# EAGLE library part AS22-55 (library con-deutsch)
DEUTSCH Connector
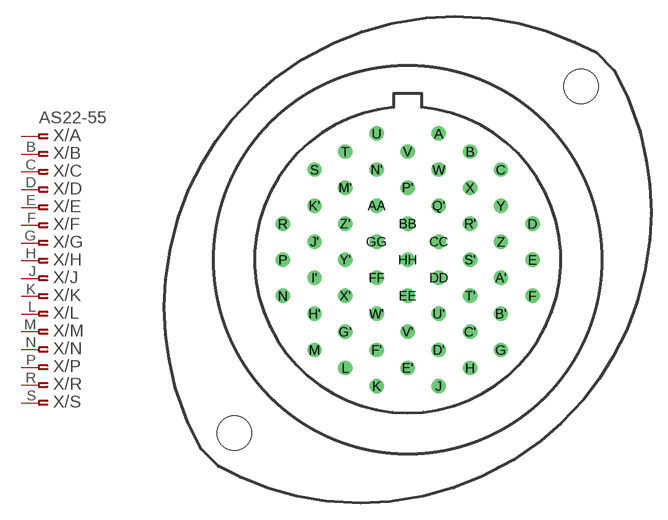
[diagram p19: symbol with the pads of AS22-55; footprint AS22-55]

Designator prefix X; gates /A=PINF_VAL /B=ASPINF /C=ASPINF /D=ASPINF /E=ASPINF /F=ASPINF /G=ASPINF /H=ASPINF /J=ASPINF /K=ASPINF /L=ASPINF /M=ASPINF /N=ASPINF /P=ASPINF /R=ASPINF /S=ASPINF /T=ASPINF /U=ASPINF /V=ASPINF /W=ASPINF /X=ASPINF /Y=ASPINF /Z=ASPINF /A'=PINF_VAL /B'=ASPINF /C'=ASPINF /D'=ASPINF /E'=ASPINF /F'=ASPINF /G'=ASPINF /H'=ASPINF /J'=ASPINF /K'=ASPINF /I'=ASPINF /M'=ASPINF /N'=ASPINF /P'=ASPINF /R'=ASPINF /S'=ASPINF /T'=ASPINF /U'=ASPINF /V'=ASPINF /W'=ASPINF /X'=ASPINF /Y'=ASPINF /Z'=ASPINF /Q'=ASPINF /AA=PINF_VAL /BB=ASPINF /CC=ASPINF /DD=ASPINF /EE=ASPINF /FF=ASPINF /GG=ASPINF /HH=ASPINF

## AS22-55 (OC_FARNELL: unknown; OC_NEWARK: unknown)  [AS22-55]
A  /A:1  pas
A'  /A':1  pas
AA  /AA:1  pas
B  /B:1  pas
B'  /B':1  pas
BB  /BB:1  pas
C  /C:1  pas
C'  /C':1  pas
CC  /CC:1  pas
D  /D:1  pas
D'  /D':1  pas
DD  /DD:1  pas
E  /E:1  pas
E'  /E':1  pas
EE  /EE:1  pas
F  /F:1  pas
F'  /F':1  pas
FF  /FF:1  pas
G  /G:1  pas
G'  /G':1  pas
GG  /GG:1  pas
H  /H:1  pas
H'  /H':1  pas
HH  /HH:1  pas
I'  /I':1  pas
J  /J:1  pas
J'  /J':1  pas
K  /K:1  pas
K'  /K':1  pas
L  /L:1  pas
M  /M:1  pas
M'  /M':1  pas
N  /N:1  pas
N'  /N':1  pas
P  /P:1  pas
P'  /P':1  pas
Q'  /Q':1  pas
R  /R:1  pas
R'  /R':1  pas
S  /S:1  pas
S'  /S':1  pas
T  /T:1  pas
T'  /T':1  pas
U  /U:1  pas
U'  /U':1  pas
V  /V:1  pas
V'  /V':1  pas
W  /W:1  pas
W'  /W':1  pas
X  /X:1  pas
X'  /X':1  pas
Y  /Y:1  pas
Y'  /Y':1  pas
Z  /Z:1  pas
Z'  /Z':1  pas

## Footprint AS22-55 (pad centres in mm)
DEUTSCH Connector
drill 0.813 round: A 2.845,11.557; A' 8.534,-1.651; AA -2.845,4.953; B 5.715,9.906; B' 8.534,-4.953; BB 0,3.302; C 8.534,8.255; C' 5.715,-6.604; CC 2.845,1.651; D 11.43,3.302; D' 2.845,-8.255; DD 2.845,-1.651; E 11.43,0; E' 0,-9.906; EE 0,-3.302; F 11.43,-3.302; F' -2.845,-8.255; FF -2.845,-1.651; G 8.534,-8.255; G' -5.715,-6.604; GG -2.845,1.651; H 5.715,-9.906; H' -8.534,-4.953; HH 0,0; I' -8.534,-1.651; J 2.845,-11.557; J' -8.534,1.651; K -2.845,-11.557; K' -8.534,4.953; L -5.715,-9.906; M -8.534,-8.255; M' -5.715,6.604; N -11.43,-3.302; N' -2.845,8.255; P -11.43,0; P' 0,6.604; Q' 2.845,4.953; R -11.43,3.302; R' 5.715,3.302; S -8.534,8.255; S' 5.715,0; T -5.715,9.906; T' 5.715,-3.302; U -2.845,11.557; U' 2.845,-4.953; V 0,9.906; V' 0,-6.604; W 2.845,8.255; W' -2.845,-4.953; X 5.715,6.604; X' -5.715,-3.302; Y 8.534,4.953; Y' -5.715,0; Z 8.534,1.651; Z' -5.715,3.302
hole 3.2 at -15.875,-15.875
hole 3.2 at 15.875,15.875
